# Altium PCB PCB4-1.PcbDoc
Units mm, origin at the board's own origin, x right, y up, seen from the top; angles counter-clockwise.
Board outline 38 x 28 mm, 2 copper layers (Top Layer, Bottom Layer); 12 components, 0 nets, 38 pads, 11 vias.
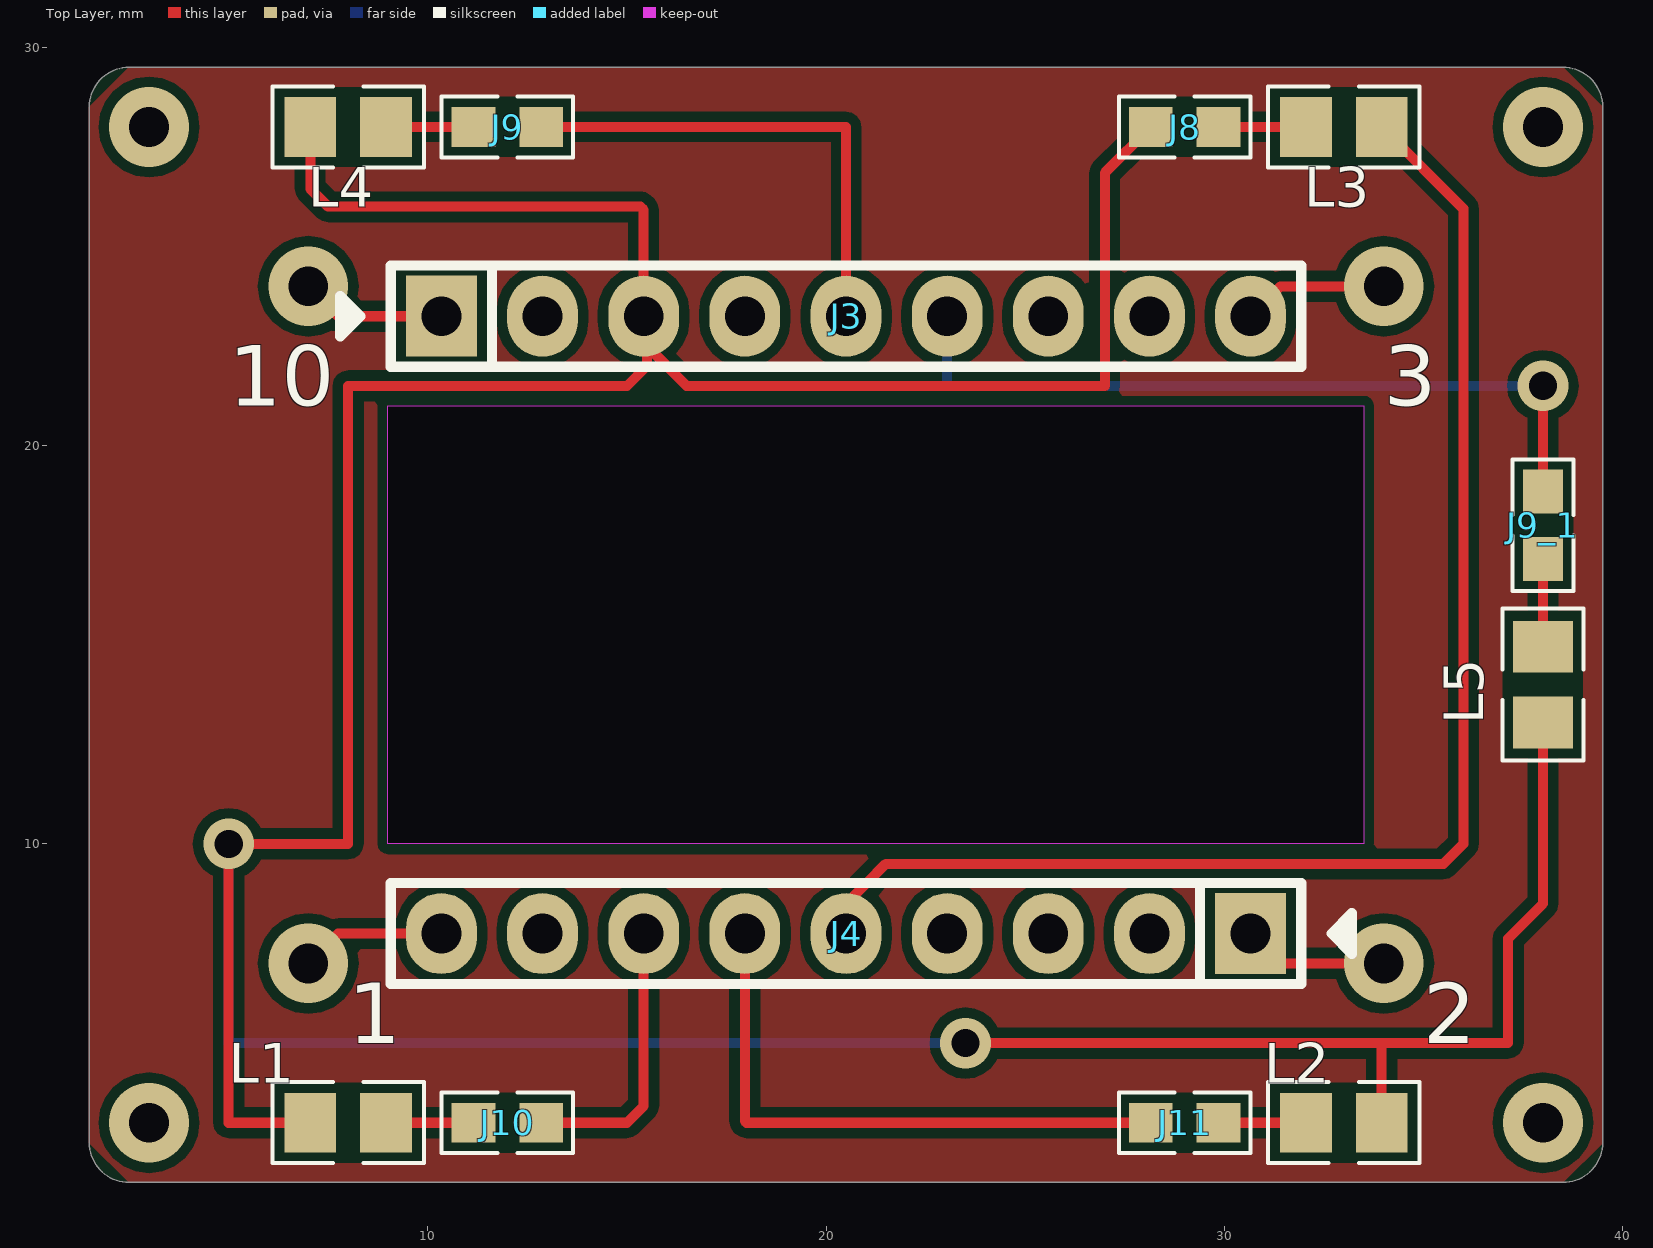
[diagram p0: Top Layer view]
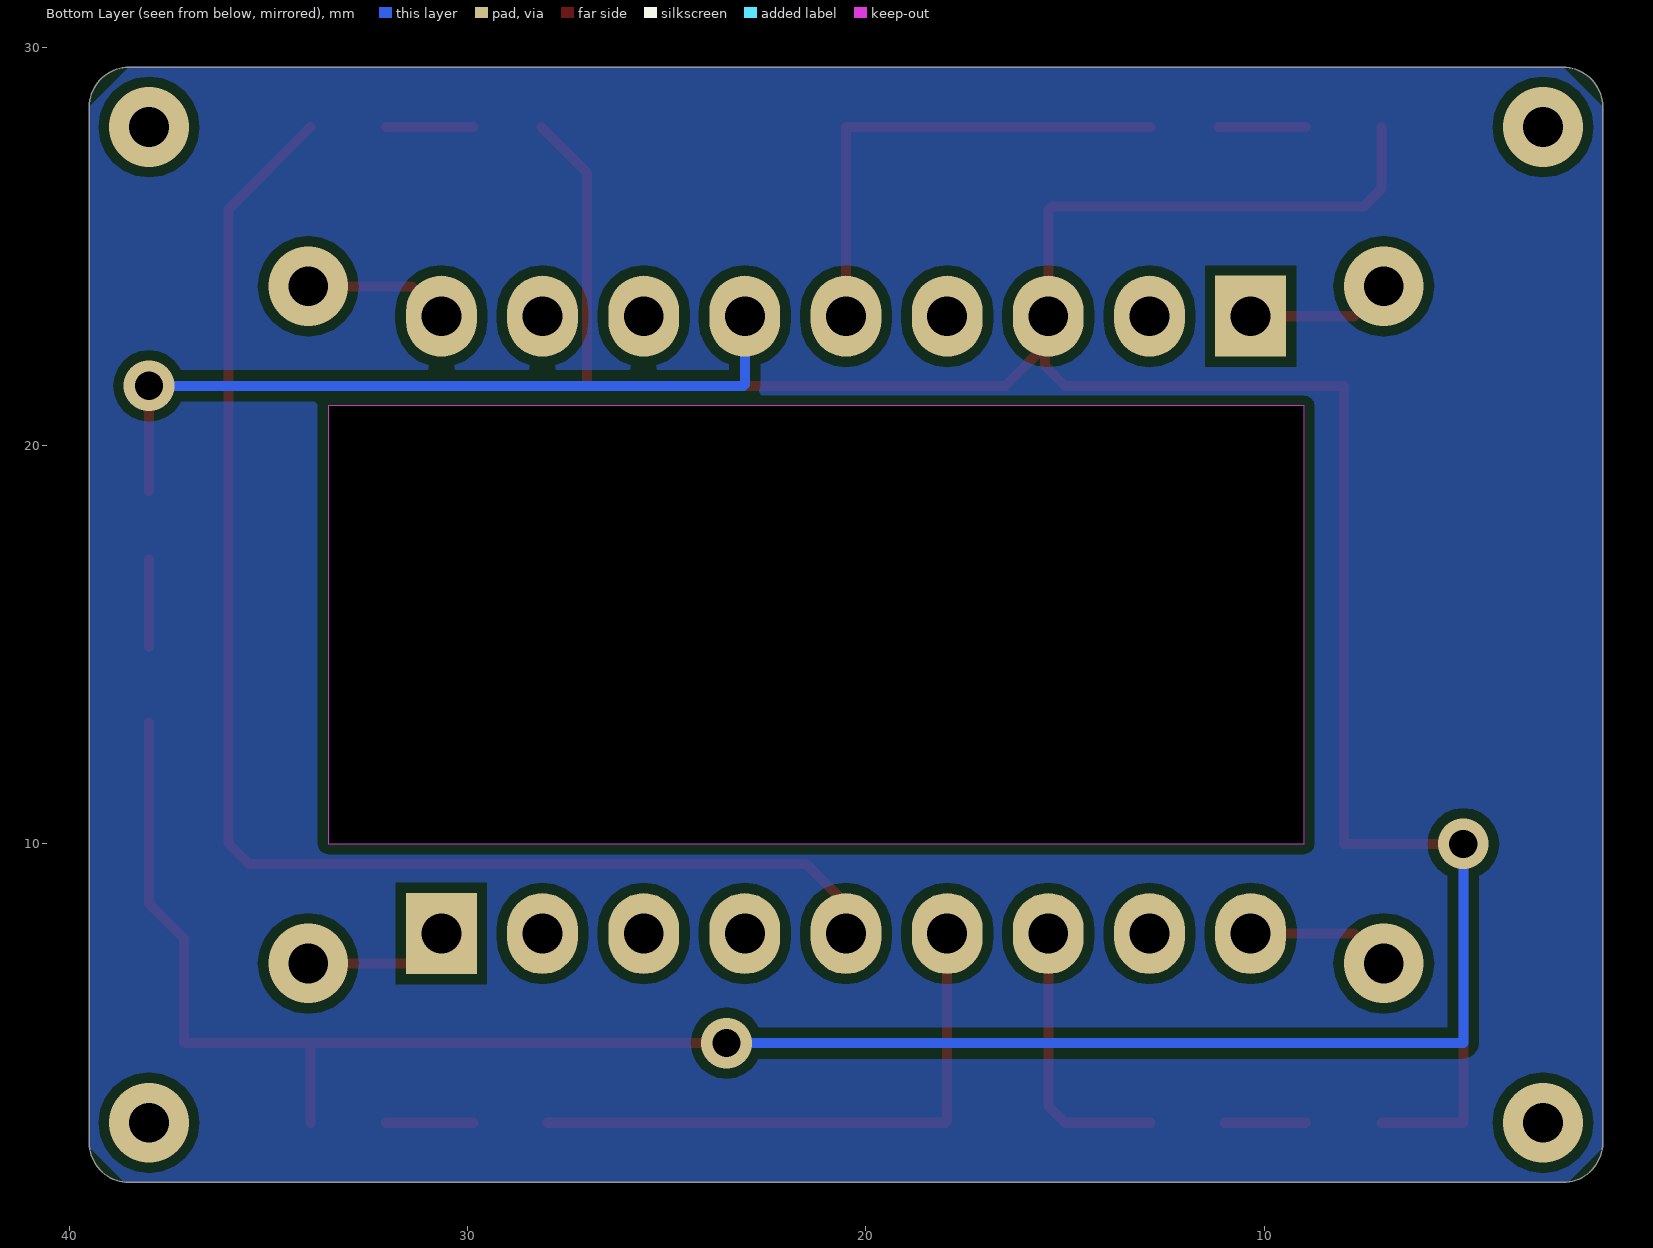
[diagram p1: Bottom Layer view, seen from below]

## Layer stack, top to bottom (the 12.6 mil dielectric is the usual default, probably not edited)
Top Solder: solder mask 0.0102, Solder Resist, Dk 3.5
Top Layer: signal copper 0.0356
Dielectric 1: dielectric 0.32, FR-4, Dk 4.8
Bottom Layer: signal copper 0.0356
Bottom Solder: solder mask 0.0102, Solder Resist, Dk 3.5

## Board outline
1.5,2.5 1.5,28.5 cw(c2.5,28.5) 2.5,29.5 38.5,29.5 cw(c38.5,28.5) 39.5,28.5 39.5,2.5 cw(c38.5,2.5) 38.5,1.5 2.5,1.5 cw(c2.5,2.5)
cut-out: 9,21 33.5,21 33.5,10 9,10

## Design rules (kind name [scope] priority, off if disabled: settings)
Clearance [All] p1: gap=0.254
PolygonConnect [All] p1: connectstyle=Relief reliefconductorwidth=0.254 reliefentries=4 polygonreliefangle="90 Angle" airgapwidth=0.254
RoutingVias [All] p1: holewidth=0.711 width=1.27 viastyle="Through Hole" minholewidth=0.711 minwidth=1.27 maxholewidth=0.711 maxwidth=1.27
SolderMaskExpansion [All] p1: expansion=0.102
Width [All] p1: maxlimit=0.254 minlimit=0.254 preferedwidth=0.254
29 further rules are at their usual default settings.

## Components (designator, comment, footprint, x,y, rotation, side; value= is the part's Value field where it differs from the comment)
J3 "Comment" PIN-9-2.54-1.0 20.5,23.25 r0 top
J4 "Comment" PIN-9-2.54-1.0 20.5,7.75 r180 top
J8 "Comment" 0603-1 29,28 r0 top
J9 "Comment" 0603-1 12,28 r0 top
J9_1 "Comment" 0603-1 38,18 r90 top
J10 "Comment" 0603-1 12,3 r0 top
J11 "Comment" 0603-1 29,3 r0 top
L1 "Comment" 0805-1 8,3 r0 top
L2 "Comment" 0805-1 33,3 r0 top
L3 "Comment" 0805-1 33,28 r0 top
L4 "Comment" 0805-1 8,28 r0 top
L5 "Comment" 0805-1 38,14 r90 top

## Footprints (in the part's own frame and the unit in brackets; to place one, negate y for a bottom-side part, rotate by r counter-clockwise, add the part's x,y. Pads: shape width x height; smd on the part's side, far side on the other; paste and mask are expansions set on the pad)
0603-1 [mm] "贴片带丝印"
  rect 1.1x1 smd: 1(-0.85,0) 2(0.85,0)
  silkscreen extent -1.65,-0.76 1.65,0.76, body extent -1.14,-0.38 1.14,0.38, height 1
0805-1 [mm] "贴片带丝印"
  rect 1.3x1.5 smd: 1(-0.95,0) 2(0.95,0)
  silkscreen extent -1.91,-1.02 1.91,1.02, body extent -1.14,-0.51 1.14,0.51, height 1
PIN-9-2.54-1.0 [mil] "Pin Header"
  rect 70x80 hole 39.37: 1(-400,0)
  oval 70x80 hole 39.37: 2(-300,0) 3(-200,0) 4(-100,0) 5(0,0) 6(100,0) 7(200,0) 8(300,0) 9(400,0)
  silkscreen extent -500,-50 450,50, body extent -450,-50 450,50, height 398

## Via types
v1: diameter 2, hole 1, Top Layer to Bottom Layer, 8 vias
v2: diameter 1.27, hole 0.711, Top Layer to Bottom Layer, tented both sides, 3 vias

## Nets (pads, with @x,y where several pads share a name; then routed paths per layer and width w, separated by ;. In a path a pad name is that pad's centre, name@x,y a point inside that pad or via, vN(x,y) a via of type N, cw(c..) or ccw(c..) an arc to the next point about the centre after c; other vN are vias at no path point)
pads on no net: J3.1 J3.2 J3.3 J3.4 J3.5 J3.6 J3.7 J3.8 J3.9 J4.1 J4.2 J4.3 J4.4 J4.5 J4.6 J4.7 J4.8 J4.9 J8.1 J8.2 J9.1 J9.2 J9_1.1 J9_1.2 J10.1 J10.2 J11.1 J11.2 L1.1 L1.2 L2.1 L2.2 L3.1 L3.2 L4.1 L4.2 L5.1 L5.2
copper on no net: | length 227
  Top Layer w0.254: v1(7,7) 7.75,7.75 10.34,7.75 ; v1(7,24) 7.75,23.25 10.34,23.25 ; 7.05,3 5,3 v2(5,10) 6.5,10 8,10 8,21.5 9.5,21.5 15,21.5 15.5,22 15.5,23 ; 7.05,28 7.05,26.45 7.5,26 15.34,26 15.42,25.92 15.42,23.25 15.42,22.58 16.5,21.5 27,21.5 27,26.85 28.15,28 ; 8.95,3 11,3 ; 8.95,28 11.15,28 ; 12.85,3 15,3 15.42,3.42 15.42,7.75 ; 12.85,28 20.5,28 20.5,23.25 ; 17.96,7.75 17.96,3.04 18,3 28,3 ; 20.5,7.75 20.5,8.5 21,9 21.5,9.5 35.5,9.5 36,10 36,25.95 33.95,28 ; v2(23.5,5) 34,5 34.5,5 37.125,5 37.125,5.875 37.125,7.625 38,8.5 38,10.5 38,13.05 ; 29.85,3 32.05,3 ; 29.85,28 32.05,28 ; 30.66,7.75 31.41,7 v1(34,7) ; 30.66,23.25 31.41,24 v1(34,24) ; 33.95,3 33.95,4.95 ; 38,14.95 38,17.15 ; 38,18.85 v2(38,21.5)
  Bottom Layer w0.254: v2(5,10) 5,5 v2(23.5,5) ; 23.04,23.25 23.04,21.54 23.08,21.5 v2(38,21.5)
  other v1: 3,3 38,3 3,28 38,28

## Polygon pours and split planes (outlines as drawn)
no net on Top Layer "Top Layer-No Net" (solid, pour order 2): 1.491,28.5 2.491,29.5 2.5,29.5 38.491,29.5 38.5,29.509 39.5,28.509 39.5,28.5 39.5,2.509 39.509,2.5 38.509,1.5 38.5,1.5 2.509,1.5 2.5,1.491 1.491,2.5 1.491,28.5
no net on Bottom Layer "Top Layer-No Net" (solid, pour order 4): 1.491,28.5 2.5,29.509 38.5,29.509 39.5,28.509 39.5,28.5 39.5,2.378 39.491,2.369 38.622,1.5 38.5,1.5 2.378,1.5 2.369,1.509 1.491,2.387 1.491,2.5 1.491,28.5

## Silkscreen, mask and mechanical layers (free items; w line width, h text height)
Top Overlay:
  text "10" at 5,21 h1.52
  text "3" at 34,21 h1.52
  text "1" at 8,5 h1.52
  text "2" at 35,5 h1.52
Mechanical 1:
  lines w0.254: 1.5,2.5 ccw(c2.5,2.5) 2.5,1.5 38.5,1.5 ccw(c38.5,2.5) 39.5,2.5 39.5,28.5 ccw(c38.5,28.5) 38.5,29.5 2.5,29.5 ccw(c2.5,28.5) 1.5,28.5 1.5,2.5 ; 9,10 10,10 33.5,10 33.5,21 9,21 9,17.25 9,10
